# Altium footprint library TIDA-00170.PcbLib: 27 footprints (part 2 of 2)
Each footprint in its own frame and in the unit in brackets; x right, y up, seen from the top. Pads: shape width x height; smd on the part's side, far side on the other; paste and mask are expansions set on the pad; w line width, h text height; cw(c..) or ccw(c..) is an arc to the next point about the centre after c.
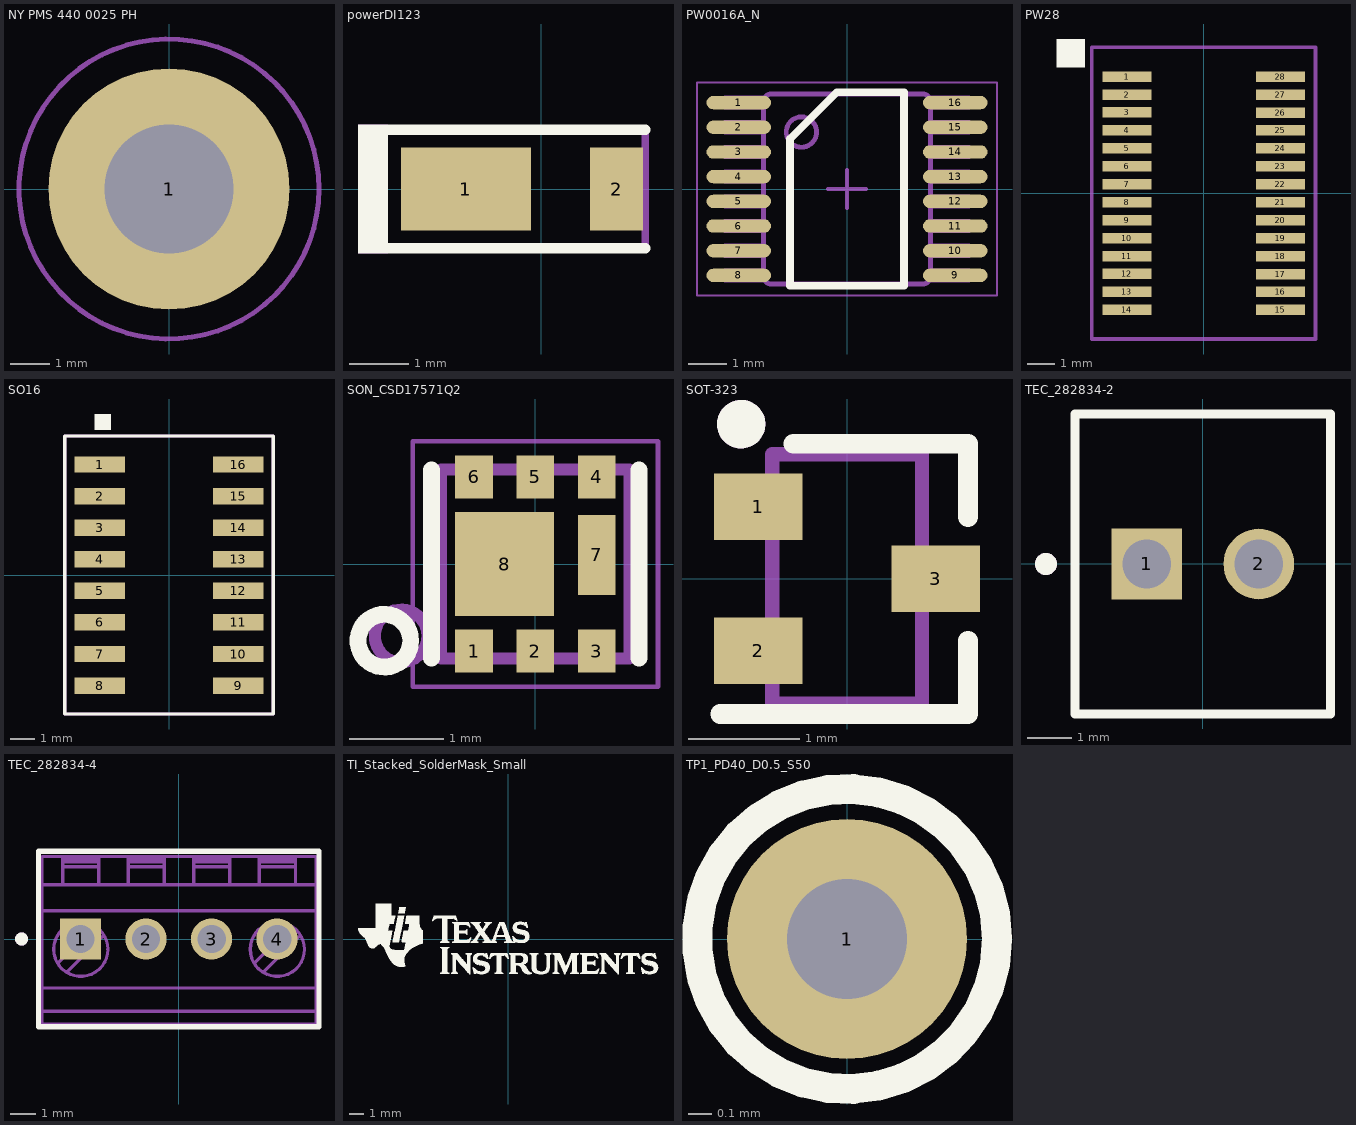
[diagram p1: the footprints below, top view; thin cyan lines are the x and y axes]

## NY PMS 440 0025 PH [mil] "4-40 nylon screw and mounting hole"
height 75
pads (1):
  round 240 hole 128: 1(0,0)
Mechanical 5:
  circle w5: c0,0 r149.16
  text ".Designator" at -170,-260 h30
3D body: height 106, standoff -344, extent -130,-129.93 129.77,129.93

## powerDI123 [mm] "Diodes Inc recommended land pattern, document number DS30628 Rev. 6-2"
height 1
pads (2):
  rect 2.2x1.4 smd: 1(-1.275,0)
  rect 0.9x1.4 smd: 2(1.275,0)
Top Overlay:
  rectangle: -3.099,-1.092 -2.591,1.092
  lines w0.178: -2.946,-1.003 1.759,-1.003 ; -2.946,1.003 1.759,1.003
Mechanical 5:
  rectangle: -3.099,-1.092 -2.591,1.092
  lines w0.127: -2.946,-1.003 1.759,-1.003 1.759,1.003 -2.946,1.003
  text ".Designator" at -2.35,-0.275 h0.76
3D body: height 1, standoff 0, extent -2.375,-0.965 1.525,0.965

## PW0016A_N [mm] "TSOP, 16-Leads, Body 5x4.4mm, Pitch 0.65mm, IPC Medium Density"
height 1.2
pads (16):
  oval 1.7x0.35 smd: 1(-2.85,2.275) 2(-2.85,1.625) 3(-2.85,0.975) 4(-2.85,0.325) 5(-2.85,-0.325) 6(-2.85,-0.975) 7(-2.85,-1.625) 8(-2.85,-2.275) 9(2.85,-2.275) 10(2.85,-1.625) 11(2.85,-0.975) 12(2.85,-0.325) 13(2.85,0.325) 14(2.85,0.975) 15(2.85,1.625) 16(2.85,2.275)
Top Overlay:
  lines w0.2: -1.5,-2.55 -1.5,1.325 -0.275,2.55 1.5,2.55 1.5,-2.55 -1.5,-2.55
Mechanical 5:
  drawing of 202 lines, arcs and shapes, not listed
  text ".Designator" at -1.854,-0.508 h1.02
Mechanical 15:
  lines w0.05: -3.95,-2.8 3.95,-2.8 3.95,2.8 -3.95,2.8 -3.95,-2.8
  lines w0.1: -0.5,0 0.5,0 ; 0,-0.5 0,0.5
3D body: height 0.98, standoff -0.02, extent -3.21,-2.5 3.21,2.5

## PW28 [mil]
pads (28):
  rect 70x15 smd: 1(-109.5,166.4) 2(-109.5,140.8) 3(-109.5,115.2) 4(-109.5,89.6) 5(-109.5,64) 6(-109.5,38.4) 7(-109.5,12.8) 8(-109.5,-12.8) 9(-109.5,-38.4) 10(-109.5,-64) 11(-109.5,-89.6) 12(-109.5,-115.2) 13(-109.5,-140.8) 14(-109.5,-166.4) 15(109.5,-166.5) 16(109.5,-140.9) 17(109.5,-115.3) 18(109.5,-89.7) 19(109.5,-64.1) 20(109.5,-38.5) 21(109.5,-12.9) 22(109.5,12.7) 23(109.5,38.3) 24(109.5,63.9) 25(109.5,89.5) 26(109.5,115.1) 27(109.5,140.7) 28(109.5,166.4)
Top Overlay:
  region: -210,180 -170,180 -170,220 -210,220
Mechanical 5:
  lines w5: -159.5,-208 159.5,-208 159.5,208 -159.5,208 -159.5,-208
  text ".Designator" at -75,-20 h40
  text "*" at -65.8,126.9 h30

## SO16 [mil]
pads (16):
  rect 80x26 smd: 1(-110,175) 2(-110,125) 3(-110,75) 4(-110,25) 5(-110,-25) 6(-110,-75) 7(-110,-125) 8(-110,-175) 9(110,-175) 10(110,-125) 11(110,-75) 12(110,-25) 13(110,25) 14(110,75) 15(110,125) 16(110,175)
Top Overlay:
  region: -92.5,255 -117.5,255 -117.5,230 -92.5,230
  lines w5: -165,-220 -165,220 165,220 165,-220 -165,-220
Mechanical 5:
  lines w5: -165,-220 165,-220 165,220 -165,220 -165,-220
  text "*" at -70,140 h30
  text ".Designator" at -75,-20 h40

## SON_CSD17571Q2 [mm] "SON, MOSFET, N-CH, 30V, 22A, SON 2X2 MM"
height 0.85
pads (8):
  rect 0.4x0.455 smd mask+0.038: 1(-0.65,-0.923) 2(0,-0.923) 5(0,0.923) 6(-0.65,0.923)
  rect 0.4x0.455 smd: 3(0.65,-0.923) 4(0.65,0.923)
  rect 0.4x0.85 smd mask+0.038: 7(0.65,0.096)
  rect 1.05x1.1 smd mask+0.038: 8(-0.325,0)
Top Overlay:
  circle w0.178: c-1.6,-0.813 r0.279
  lines w0.178: -1.1,-1 -1.1,1 ; 1.1,-1 1.1,1
  text ".Designator" at -1.397,0.127 h1.02
Mechanical 5:
  circle w0.127: c-1.422,-0.762 r0.279
  lines w0.127: -1,-1 1,-1 1,1 -1,1 -1,-1
  text ".Designator" at 0.381,-0.508 h0.76
Mechanical 15:
  lines w0.05: -1.3,-1.3 -1.3,1.3 1.3,1.3 1.3,-1.3 -1.3,-1.3
3D body: height 0.85, standoff 0, extent -1,-1 1,0.975

## SOT-323 [mm] "Zetex recommended land pattern.  March 2007"
height 1.1
pads (3):
  rect 0.8x0.6 smd: 1(-0.8,0.65) 2(-0.8,-0.65) 3(0.8,0)
Top Overlay:
  circle w0.254: c-0.955,1.397 r0.092
  lines w0.178: -1.143,-1.219 1.092,-1.219 1.092,-0.559 ; -0.483,1.219 1.092,1.219 1.092,0.559
Mechanical 5:
  circle w0.254: c-0.955,1.397 r0.092
  lines w0.127: -1.125,-0.8 -1.125,-0.5 -0.975,-0.5 -0.935,-0.5 -0.884,-0.5 -0.725,-0.5 -0.675,-0.5 -0.675,-0.8 -0.725,-0.8 -0.884,-0.8 -0.935,-0.8 -0.975,-0.8 -1.125,-0.8 ; -1.125,0.5 -1.125,0.8 -0.975,0.8 -0.935,0.8 -0.884,0.8 -0.725,0.8 -0.675,0.8 -0.675,0.5 -0.725,0.5 -0.884,0.5 -0.935,0.5 -0.975,0.5 -1.125,0.5 ; -0.675,-1.125 -0.675,1.125 0.675,1.125 0.675,-1.125 -0.675,-1.125 ; 0.675,-0.15 0.725,-0.15 0.884,-0.15 0.935,-0.15 0.975,-0.15 1.125,-0.15 1.125,0.15 0.975,0.15 0.935,0.15 0.884,0.15 0.725,0.15 0.675,0.15 0.675,-0.15
  text ".Designator" at -0.25,0.925 h0.51
3D body: height 1.13, standoff 0.02, extent -1.125,-1.125 1.125,1.125

## TEC_282834-2 [mm] "TEC"
height 10.3
pads (2):
  rect 1.6x1.6 hole 1.1: 1(-1.27,0)
  round 1.6 hole 1.1: 2(1.27,0)
Top Overlay:
  circle w0.3: c-3.556,0 r0.1
  lines w0.2: -2.895,-3.4 2.895,-3.4 2.895,3.4 -2.895,3.4 -2.895,-3.4
Mechanical 5:
  circle w0.3: c-3.556,0 r0.1
  lines w0.1: -2.895,-3.4 2.895,-3.4 2.895,3.4 -2.895,3.4 -2.895,-3.4
  text ".Designator" at -0.002,2.878 h1.27
3D body: height 10.01, standoff -3.39, extent -2.77,-3.25 2.77,3.25

## TEC_282834-4 [mm] "TEC"
height 10.3
pads (4):
  rect 1.6x1.6 hole 1.1: 1(-3.81,0)
  round 1.6 hole 1.1: 2(-1.27,0) 3(1.27,0) 4(3.81,0)
Top Overlay:
  circle w0.3: c-6.096,0 r0.1
  lines w0.2: -5.435,-3.4 -5.435,3.4 5.435,3.4 5.435,-3.4 -5.435,-3.4
Mechanical 5:
  circle w0.3: c-6.096,0 r0.1
  lines w0.127: -4.698,-0.944 -3.256,0.498 ; -4.5,2.8 -3.1,2.8 ; -4.5,3 -3.1,3 ; -4.5,3.1 -3.1,3.1 ; -4.344,-1.298 -2.902,0.144 ; -1.96,2.8 -0.56,2.8 ; -1.96,3 -0.56,3 ; -1.96,3.1 -0.56,3.1 ; 0.58,2.8 1.98,2.8 ; 0.58,3 1.98,3 ; 0.58,3.1 1.98,3.1 ; 2.922,-0.944 4.364,0.498 ; 3.12,2.8 4.52,2.8 ; 3.12,3 4.52,3 ; 3.12,3.1 4.52,3.1 ; 3.276,-1.298 4.718,0.144 ; -5.3,-2.8 -5.3,-1.9 ; -5.3,-2.8 -5.3,-3.3 5.32,-3.3 5.32,-2.8 ; -5.3,-2.8 5.32,-2.8 ; -5.3,-1.9 5.32,-1.9 ; -5.3,-1.9 -5.3,1.1 ; -5.3,1.1 5.32,1.1 ; -5.3,1.1 -5.3,2.1 ; -5.3,2.1 -4.5,2.1 ; -5.3,2.1 -5.3,2.9 -5.3,3.2 -4.5,3.2 ; -4.5,2.1 -3.1,2.1 ; -4.5,2.1 -4.5,2.9 -4.5,3.2 ; -4.5,3.2 -3.1,3.2 ; -3.1,2.1 -3.1,2.9 -3.1,3.2 ; -3.1,2.1 -1.96,2.1 ; -3.1,3.2 -1.96,3.2 ; -1.96,2.1 -1.96,2.9 -1.96,3.2 ; -1.96,2.1 -0.56,2.1 ; -1.96,3.2 -0.56,3.2 ; -0.56,2.1 0.58,2.1 ; -0.56,2.1 -0.56,2.9 -0.56,3.2 ; -0.56,3.2 0.58,3.2 ; 0.58,2.1 1.98,2.1 ; 0.58,2.1 0.58,2.9 0.58,3.2 ; 0.58,3.2 1.98,3.2 ; 1.98,2.1 3.12,2.1 ; 1.98,2.1 1.98,2.9 1.98,3.2 ; 1.98,3.2 3.12,3.2 ; 3.12,2.1 3.12,2.9 3.12,3.2 ; 3.12,2.1 4.52,2.1 ; 3.12,3.2 4.52,3.2 ; 4.52,2.1 4.52,2.9 4.52,3.2 ; 4.52,2.1 5.32,2.1 ; 4.52,3.2 5.32,3.2 5.32,2.9 5.32,2.1 ; 5.32,-2.8 5.32,-1.9 ; 5.32,-1.9 5.32,1.1 ; 5.32,1.1 5.32,2.1 ; -4.85,-0.4 ccw(c-3.8,-0.4) -2.75,-0.4 ccw(c-3.8,-0.4) -4.85,-0.4 ; 2.77,-0.4 ccw(c3.82,-0.4) 4.87,-0.4 ccw(c3.82,-0.4) 2.77,-0.4
  text ".Designator" at -5.207,-4.826 h1.02
3D body: height 10.02, standoff -3.38, extent -5.31,-3.25 5.31,3.25

## TI_Stacked_SolderMask_Small [mm]
Top Overlay:
  drawing of 18 lines, arcs and shapes, not listed

## TP1_PD40_D0.5_S50 [mil]
height 1.4
pads (1):
  round 40 hole 20: 1(0,0)
Top Overlay:
  circle w5: c0,0 r25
